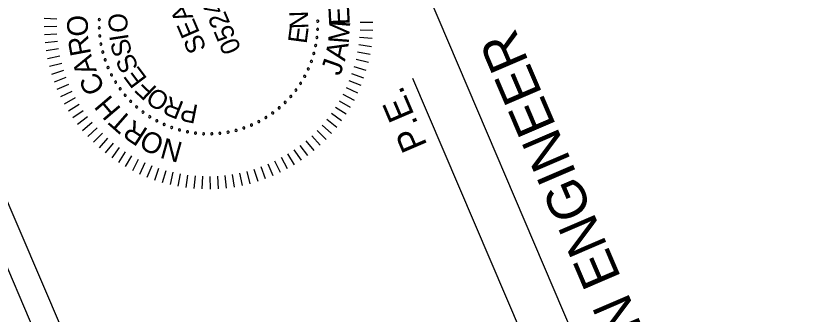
# Model space of a CAD drawing. Extents: x 1550250 to 1553210, y 808906 to 812497.
# Drawn here: x 1551944.7 to 1552205.6, y 811523.5 to 811622.3 of the extents above; entities that cross this region are included whole.
import ezdxf

# ---------------------------------------------------------------- set-up
doc = ezdxf.new("R2010")
doc.units = 0
doc.layers.add('Old_Level_50', color=7, linetype='Continuous')
doc.layers.add('Sheet_Title_CELL', color=7, linetype='Continuous')

msp = doc.modelspace()

# ---------------------------------------------------------------- linework, layer by layer
at = {"layer": 'Old_Level_50'}
for p, q in [((1551954.17, 811621.47), (1551958.36, 811621.31)), ((1551954.14, 811618.79), (1551958.33, 811618.84)), ((1552063.17, 811620.07), (1552058.97, 811620.03)), ((1551954.23, 811616.12), (1551958.42, 811616.37)), ((1552063.13, 811617.4), (1552058.94, 811617.56)), ((1551954.46, 811613.45), (1551958.63, 811613.91)), ((1552062.97, 811614.73), (1552058.79, 811615.09)), ((1551954.82, 811610.8), (1551958.96, 811611.46)), ((1552062.67, 811612.07), (1552058.51, 811612.64)), ((1551955.31, 811608.17), (1551959.41, 811609.04)), ((1552061.69, 811606.81), (1552057.61, 811607.78)), ((1552062.24, 811609.43), (1552058.12, 811610.2)), ((1551955.92, 811605.57), (1551959.98, 811606.63)), ((1552061, 811604.22), (1552056.98, 811605.39)), ((1551956.67, 811603), (1551960.67, 811604.26)), ((1552060.19, 811601.67), (1552056.23, 811603.04)), ((1551957.54, 811600.46), (1551961.47, 811601.92)), ((1552059.26, 811599.16), (1552055.37, 811600.72)), ((1551958.53, 811597.98), (1551962.39, 811599.63)), ((1551959.64, 811595.55), (1551963.41, 811597.38)), ((1552058.21, 811596.71), (1552054.39, 811598.45)), ((1551960.87, 811593.17), (1551964.55, 811595.19)), ((1552057.03, 811594.3), (1552053.31, 811596.23)), ((1551962.22, 811590.86), (1551965.79, 811593.06)), ((1552055.74, 811591.96), (1552052.12, 811594.07)), ((1551963.68, 811588.61), (1551967.14, 811590.98)), ((1552052.82, 811587.47), (1552049.42, 811589.93)), ((1552054.33, 811589.68), (1552050.82, 811591.97)), ((1552115.96, 811589.53), (1552115.96, 811589.53)), ((1551965.25, 811586.44), (1551968.58, 811588.98)), ((1551966.92, 811584.35), (1551970.13, 811587.05)), ((1552051.2, 811585.35), (1552047.92, 811587.97)), ((1551968.69, 811582.35), (1551971.76, 811585.2)), ((1552049.47, 811583.3), (1552046.33, 811586.08)), ((1551970.56, 811580.43), (1551973.49, 811583.43)), ((1551972.52, 811578.61), (1551975.29, 811581.75)), ((1552045.74, 811579.47), (1552042.88, 811582.55)), ((1552047.65, 811581.34), (1552044.65, 811584.27)), ((1551974.56, 811576.89), (1551977.18, 811580.16)), ((1552041.64, 811576.03), (1552039.1, 811579.37)), ((1552043.73, 811577.7), (1552041.03, 811580.91)), ((1551976.69, 811575.27), (1551979.15, 811578.66)), ((1551978.9, 811573.75), (1551981.19, 811577.26)), ((1552037.23, 811573), (1552035.03, 811576.58)), ((1552039.47, 811574.46), (1552037.1, 811577.92)), ((1551981.17, 811572.35), (1551983.29, 811575.97)), ((1551983.52, 811571.05), (1551985.45, 811574.78)), ((1552032.54, 811570.43), (1552030.7, 811574.2)), ((1552034.91, 811571.66), (1552032.89, 811575.33)), ((1551985.92, 811569.88), (1551987.67, 811573.69)), ((1551988.38, 811568.82), (1551989.94, 811572.72)), ((1551990.89, 811567.89), (1551992.25, 811571.85)), ((1552025.09, 811567.45), (1552023.82, 811571.45)), ((1552027.62, 811568.32), (1552026.16, 811572.25)), ((1552030.1, 811569.31), (1552028.45, 811573.17)), ((1551993.44, 811567.08), (1551994.61, 811571.11)), ((1551996.03, 811566.4), (1551997, 811570.48)), ((1551998.64, 811565.84), (1551999.41, 811569.96)), ((1552001.29, 811565.41), (1552001.85, 811569.57)), ((1552003.94, 811565.12), (1552004.31, 811569.3)), ((1552006.62, 811564.95), (1552006.77, 811569.14)), ((1552009.29, 811564.92), (1552009.24, 811569.11)), ((1552011.97, 811565.02), (1552011.71, 811569.2)), ((1552014.63, 811565.24), (1552014.17, 811569.41)), ((1552017.28, 811565.6), (1552016.62, 811569.74)), ((1552019.91, 811566.09), (1552019.05, 811570.19)), ((1552022.52, 811566.71), (1552021.45, 811570.76))]:
    msp.add_line(p, q, dxfattribs=at)
for centre, start, end in [((1551972.45, 811621.04), 10.3165, 190.3165), ((1551972.45, 811621.04), 190.3165, 10.3165), ((1552044.87, 811620.54), 10.3165, 190.3165), ((1551972.43, 811618.33), 10.3165, 190.3165), ((1551972.43, 811618.33), 190.3165, 10.3165), ((1552044.87, 811620.54), 190.3165, 10.3165), ((1551972.62, 811615.63), 10.3165, 190.3165), ((1551972.62, 811615.63), 190.3165, 10.3165), ((1552044.85, 811617.83), 10.3165, 190.3165), ((1552044.85, 811617.83), 190.3165, 10.3165), ((1551973, 811612.94), 10.3165, 190.3165), ((1551973, 811612.94), 190.3165, 10.3165), ((1552044.63, 811615.13), 10.3165, 190.3165), ((1552044.63, 811615.13), 190.3165, 10.3165), ((1551973.59, 811610.3), 10.3165, 190.3165), ((1552044.2, 811612.45), 10.3165, 190.3165), ((1552044.2, 811612.45), 190.3165, 10.3165), ((1551973.59, 811610.3), 190.3165, 10.3165), ((1551974.37, 811607.7), 10.3165, 190.3165), ((1552043.58, 811609.81), 10.3165, 190.3165), ((1552043.58, 811609.81), 190.3165, 10.3165), ((1551974.37, 811607.7), 190.3165, 10.3165), ((1551975.34, 811605.18), 10.3165, 190.3165), ((1551975.34, 811605.18), 190.3165, 10.3165), ((1552042.77, 811607.23), 10.3165, 190.3165), ((1552042.77, 811607.23), 190.3165, 10.3165), ((1551976.5, 811602.73), 10.3165, 190.3165), ((1551976.5, 811602.73), 190.3165, 10.3165), ((1552040.57, 811602.28), 10.3165, 190.3165), ((1552041.76, 811604.71), 10.3165, 190.3165), ((1552041.76, 811604.71), 190.3165, 10.3165), ((1551977.84, 811600.37), 10.3165, 190.3165), ((1551977.84, 811600.37), 190.3165, 10.3165), ((1552039.2, 811599.94), 10.3165, 190.3165), ((1552039.2, 811599.94), 190.3165, 10.3165), ((1552040.57, 811602.28), 190.3165, 10.3165), ((1551979.35, 811598.12), 10.3165, 190.3165), ((1551979.35, 811598.12), 190.3165, 10.3165), ((1552037.65, 811597.72), 10.3165, 190.3165), ((1552037.65, 811597.72), 190.3165, 10.3165), ((1551981.02, 811595.99), 10.3165, 190.3165), ((1551981.02, 811595.99), 190.3165, 10.3165), ((1552035.95, 811595.61), 10.3165, 190.3165), ((1552035.95, 811595.61), 190.3165, 10.3165), ((1551982.85, 811593.99), 10.3165, 190.3165), ((1551982.85, 811593.99), 190.3165, 10.3165), ((1551984.83, 811592.13), 10.3165, 190.3165), ((1551984.83, 811592.13), 190.3165, 10.3165), ((1552032.09, 811591.81), 10.3165, 190.3165), ((1552034.09, 811593.64), 10.3165, 190.3165), ((1552034.09, 811593.64), 190.3165, 10.3165), ((1551986.93, 811590.43), 10.3165, 190.3165), ((1551986.93, 811590.43), 190.3165, 10.3165), ((1552029.96, 811590.13), 10.3165, 190.3165), ((1552029.96, 811590.13), 190.3165, 10.3165), ((1552032.09, 811591.81), 190.3165, 10.3165), ((1551989.16, 811588.89), 10.3165, 190.3165), ((1551989.16, 811588.89), 190.3165, 10.3165), ((1551991.5, 811587.52), 10.3165, 190.3165), ((1551991.5, 811587.52), 190.3165, 10.3165), ((1552025.36, 811587.28), 10.3165, 190.3165), ((1552025.36, 811587.28), 190.3165, 10.3165), ((1552027.71, 811588.62), 10.3165, 190.3165), ((1552027.71, 811588.62), 190.3165, 10.3165), ((1551993.93, 811586.32), 10.3165, 190.3165), ((1551993.93, 811586.32), 190.3165, 10.3165), ((1551996.45, 811585.32), 10.3165, 190.3165), ((1551996.45, 811585.32), 190.3165, 10.3165), ((1551999.03, 811584.5), 10.3165, 190.3165), ((1551999.03, 811584.5), 190.3165, 10.3165), ((1552017.79, 811584.37), 10.3165, 190.3165), ((1552017.79, 811584.37), 190.3165, 10.3165), ((1552020.38, 811585.15), 10.3165, 190.3165), ((1552020.38, 811585.15), 190.3165, 10.3165), ((1552022.91, 811586.12), 10.3165, 190.3165), ((1552022.91, 811586.12), 190.3165, 10.3165), ((1552001.67, 811583.88), 10.3165, 190.3165), ((1552001.67, 811583.88), 190.3165, 10.3165), ((1552004.34, 811583.46), 10.3165, 190.3165), ((1552004.34, 811583.46), 190.3165, 10.3165), ((1552007.04, 811583.24), 10.3165, 190.3165), ((1552007.04, 811583.24), 190.3165, 10.3165), ((1552009.75, 811583.22), 10.3165, 190.3165), ((1552009.75, 811583.22), 190.3165, 10.3165), ((1552012.46, 811583.4), 10.3165, 190.3165), ((1552012.46, 811583.4), 190.3165, 10.3165), ((1552015.14, 811583.79), 10.3165, 190.3165), ((1552015.14, 811583.79), 190.3165, 10.3165)]:
    msp.add_arc(centre, 0.352, start, end, dxfattribs=at)
at = {"layer": 'Sheet_Title_CELL'}
for p, q in [((1552747.76, 809656.43), (1551686.13, 812136.57)), ((1552195.84, 811362.24), (1552046.65, 811710.76)), ((1552046.33, 811317), (1551910.72, 811633.8)), ((1552172.46, 811377.09), (1552076.42, 811601.49))]:
    msp.add_line(p, q, dxfattribs=at)

# ---------------------------------------------------------------- texts
at = {"layer": 'Old_Level_50'}
for s, height, rotation, p in [('052432', 6.291, 113.1736, (1552019.61, 811611.28)), ('SEAL', 6.291, 113.1736, (1552008.11, 811611.5)), ('E', 6.87, 92.8185, (1552055.57, 811619.29)), ('O', 6.87, 91.7383, (1551968.77, 811615.52)), ('O', 6.25, 90.5721, (1551981.82, 811616.71)), ('N', 6.25, 91.7477, (1552041.82, 811617.99)), ('E', 6.25, 82.4051, (1552041.17, 811612.85)), ('M', 6.87, 85.5613, (1552055.14, 811612.87)), ('R', 6.87, 100.4178, (1551969.79, 811609.67)), ('I', 6.25, 98.612, (1551982.24, 811614.42)), ('S', 6.25, 106.1776, (1551983.48, 811609.81)), ('A', 6.87, 77.7044, (1552053.91, 811607.06)), ('A', 6.87, 109.0974, (1551971.67, 811604.03)), ('S', 6.25, 116.8345, (1551985.69, 811605.32)), ('J', 6.87, 70.7472, (1552052.24, 811602.13)), ('E', 6.25, 127.0166, (1551988.55, 811601.48)), ('C', 6.87, 118.1281, (1551974.6, 811598.31)), ('F', 6.25, 136.724, (1551991.86, 811598.35)), ('O', 6.25, 147.3804, (1551996.24, 811595.49)), ('H', 6.87, 130.389, (1551979.95, 811591.47)), ('R', 6.25, 158.2743, (1552000.89, 811593.62)), ('P', 6.25, 168.4566, (1552005.57, 811592.65)), ('T', 6.87, 138.7174, (1551983.84, 811588.01)), ('R', 6.87, 146.8702, (1551988.96, 811584.54)), ('O', 6.87, 155.5497, (1551994.56, 811581.92)), ('N', 6.87, 164.4049, (1552000.5, 811580.2))]:
    msp.add_text(s, height=height, rotation=rotation, dxfattribs=at).set_placement(p)
at = {"layer": 'Sheet_Title_CELL'}
for s, height, p in [('ROADWAY DESIGN ENGINEER', 12.9365, (1552210.67, 811383.56)), ('P.E.', 8.624, (1552081.32, 811579.48))]:
    msp.add_text(s, height=height, rotation=113.1736, dxfattribs=at).set_placement(p)

doc.saveas('drawing.dxf')
